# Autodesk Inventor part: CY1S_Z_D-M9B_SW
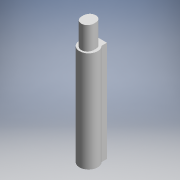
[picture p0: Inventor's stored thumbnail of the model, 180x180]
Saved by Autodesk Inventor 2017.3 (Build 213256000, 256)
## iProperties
Part Number: CY1S_Z_D-M9B_SW
Material: Generic
Catalog Web Link: www.cadenas.de
Description: CY1S-Z_SW-Magnetically Coupled Rodless Cylinder Slider Type/Slide Bearing
Vendor: SMC
Document SubType Name: Modeling
Designer: partserver
Manufacturer: SMC
Mass: 0.359523 g
Surface Area: 4.00035 cm^2
Volume: 0.359523 cm^3
Density: 1 g/cm^3
Appearance: PSOLRGB-255-255-255
Category: PARTsolutions
Company: SMC
Title: CY1S_Z_D-M9B_SW
Author: Cadenas PARTsolutions
Comments: Magnetically Coupled Rodless Cylinder Slider Type/Slide Bearing
PSOL_IDENT_0: {$CADENAS_DATA\23d-libs\smc_jp\actuator\rodless_cylinders\cy1\cy1s_z\parts\cy1s_z_sw.prj},183 {VTYP=
PSOL_IDENT_1: 3D},{NB=CY1S_Z_D-M9B_SW},{LINA=CY1S_Z_D-M9B_SW},{NN=CY1S-Z_SW},{DATE=09.12.2020 02:54:14},{GEOMDATE=
PSOL_IDENT_2: 09.03.2020 08:58:35},{VERSION=},{LINEID=10},{WBVAR=AUTOSWITCH},{WBNUMERIC=}  {NB=CY1S_Z_D-M9B_SW},{L
PSOL_IDENT_3: INA=CY1S_Z_D-M9B_SW},{KT=DUMMY},{AUTOSWITCH=-M9B},{ASL=22},{THREAD2=MIN},{POS=MIN},{STOP=MIN}
NB: CY1S_Z_D-M9B_SW
NN: CY1S-Z_SW
NT: Magnetically Coupled Rodless Cylinder Slider Type/Slide Bearing
NBSYN: CY1S_Z_D$AUTOSWITCH._SW
LINA: CY1S_Z_D-M9B_SW
CATALOG: SMC (JP
AUTOSWITCH: M9B
THREAD2: 0
POS: 0
STOP: 0
SUPPLIER: SMC
ARTICLENO: CY1S_Z_D-M9B_SW
BOMINFO: CY1S_Z_D-M9B_SW
CREATOR: CADENAS GmbH
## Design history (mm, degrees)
sketch "Sketch_4"
  geometry: L1 (1.4, 1.428)-(1.4, 2.6); L2 (1.4, 2.6)-(-1.4, 2.6); L3 (-1.4, 2.6)-(-1.4, 1.428); A1 r 2 centre (0, 0) between (-1.4, 1.428) and (1.4, 1.428)
  constraints: 6 end point, 2 point on circle, 1 centre point
extrude "Extrusion1" join sketch "Sketch_4" distance "d0" = 22; taper "d1" = 0 deg
sketch "Sketch_20"
  geometry: C1 r 1.25 at (0, 2); C2 r 1.05 at (0, 2); 2 further points
  constraints: 2 centre point
extrude "Extrusion2" cut sketch "Sketch_20" distance "d2" = 0.1; taper "d3" = 0 deg
sketch "Sketch_19"
  geometry: L1 (-0.544, 1.102)-(0.898, 2.544); L2 (0.544, 2.898)-(-0.898, 1.456); A1 r 1.05 centre (0, 2) between (-0.898, 1.456) and (-0.544, 1.102); A2 r 1.05 centre (0, 2) between (0.898, 2.544) and (0.544, 2.898)
  constraints: 4 end point, 4 point on circle, 2 centre point
extrude "Extrusion3" cut sketch "Sketch_19" distance "d4" = 0.1; taper "d5" = 0 deg
sketch "Sketch_8"
  geometry: L1 (-1.35, 0.25)-(-1.35, -0.25); L2 (1.35, -0.25)-(1.35, 0.25); A1 r 1.35 centre (0, -0.25) between (-1.35, -0.25) and (0, -1.6); A2 r 1.35 centre (0, -0.25) between (0, -1.6) and (1.35, -0.25); A3 r 1.35 centre (0, 0.25) between (1.35, 0.25) and (0, 1.6); A4 r 1.35 centre (0, 0.25) between (0, 1.6) and (-1.35, 0.25)
  constraints: 8 point on circle, 4 centre point, 4 end point
extrude "Extrusion4" join sketch "Sketch_8" distance "d6" = 5; taper "d7" = 0 deg
node "SW_XY"
node "SW_YZ"
node "SW_ZX"
node "SW_X"
node "SW_Y"
node "SW_Z"
node "SW_Center"
body "Solid1"
other parameters: "d8" = 0
